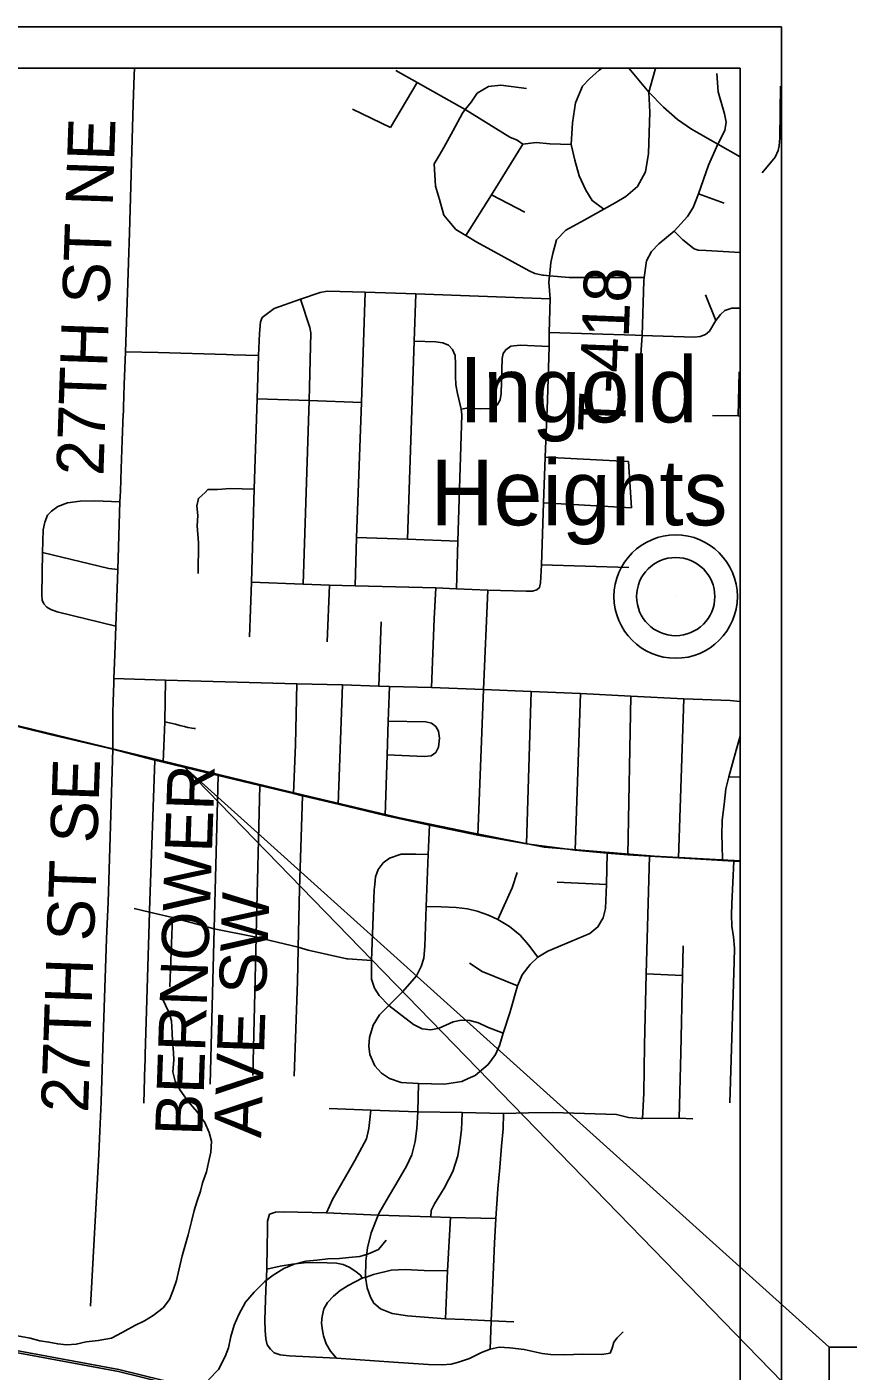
# Model space of a CAD drawing. Extents: x 25.6 to 80.6, y 0.2 to 24.5.
# Drawn here: x 46.093 to 48.073, y 14.588 to 17.83 of the extents above; entities that cross this region are included whole.
import ezdxf

# ---------------------------------------------------------------- set-up
doc = ezdxf.new("R2010")
doc.units = 0
for name, color, linetype in [('GM_X_Minor_Lake', 7, 'Continuous'), ('GM_X_Minor_River', 7, 'Continuous'), ('GM_X_Rail_Line', 7, 'Continuous'), ('GM_X_State_Route', 7, 'Continuous'), ('GM_X_Township_Road', 7, 'Continuous'), ('GM_X_Township_Road_Text', 7, 'Continuous'), ('GM_X_Unincorporated', 7, 'Continuous'), ('GM_X_Unincorporated_Location', 7, 'Continuous'), ('GM_X_Unincorporated_Text', 7, 'Continuous'), ('SH_Data', 7, 'Continuous'), ('SH_Text', 7, 'Continuous')]:
    doc.layers.add(name, color=color, linetype=linetype)

msp = doc.modelspace()

# ---------------------------------------------------------------- linework, layer by layer
at = {"layer": 'GM_X_Minor_Lake'}
msp.add_lwpolyline([(46.5313, 14.5669), (46.5552, 14.5923), (46.5715, 14.6237), (46.5795, 14.6443), (46.5852, 14.6718), (46.5925, 14.6992), (46.6043, 14.7245), (46.6205, 14.7543), (46.6407, 14.7789), (46.6669, 14.8044), (46.6872, 14.8198), (46.7128, 14.8354), (46.7376, 14.8464), (46.7656, 14.8529), (46.7921, 14.8555), (46.8187, 14.8589), (46.8467, 14.8601), (46.8694, 14.8619), (46.896, 14.8646), (46.9171, 14.8709), (46.9413, 14.8812), (46.9591, 14.9042)], dxfattribs=at)
at = {"layer": 'GM_X_Minor_River'}
msp.add_lwpolyline([(46.0701, 14.6736), (46.1013, 14.6672), (46.1241, 14.6615), (46.1462, 14.658), (46.1675, 14.6537), (46.1887, 14.6517), (46.2122, 14.6528), (46.2357, 14.6585), (46.2652, 14.6619), (46.297, 14.6677), (46.3226, 14.681), (46.3535, 14.6981), (46.3769, 14.7091), (46.3972, 14.7223), (46.4219, 14.7409), (46.4368, 14.7609), (46.4456, 14.783), (46.4537, 14.8067), (46.4594, 14.8318), (46.4673, 14.8661), (46.4752, 14.8944), (46.4818, 14.9165), (46.4897, 14.9493), (46.4961, 14.9752), (46.5034, 14.9989), (46.5114, 15.0225), (46.5165, 15.0424), (46.526, 15.0691), (46.531, 15.0912), (46.5367, 15.1163), (46.5379, 15.143), (46.5323, 15.1634), (46.5221, 15.1876), (46.5028, 15.2139), (46.4819, 15.2387), (46.4626, 15.2658), (46.4509, 15.2876), (46.4453, 15.3096), (46.4472, 15.3377), (46.4462, 15.3567), (46.4443, 15.384), (46.4433, 15.4038), (46.4414, 15.4326), (46.435, 15.4538), (46.4194, 15.4878)], dxfattribs=at)
at = {"layer": 'GM_X_Rail_Line'}
for points in [[(47.8128, 15.8191), (47.6057, 15.8302), (47.3402, 15.8521), (47.1631, 15.8871), (46.9912, 15.9223), (46.7273, 15.9853), (45.9383, 16.1769), (45.6136, 16.2567), (45.5036, 16.2842), (45.3992, 16.2924), (45.0499, 16.3176), (44.9789, 16.3252), (44.6728, 16.4383), (44.4128, 16.5397)], [(44.4128, 14.8771), (44.4231, 14.8756), (44.5249, 14.8648), (44.6048, 14.8557), (44.6465, 14.8507), (44.805, 14.8274), (45.0669, 14.7959), (45.2891, 14.7633), (46.0102, 14.6483), (46.3148, 14.5918), (46.4227, 14.5651), (46.528, 14.5372), (46.6857, 14.4857), (46.9234, 14.4078), (47.0403, 14.372), (47.1373, 14.3511), (47.2255, 14.3378), (47.2936, 14.3374), (47.3809, 14.3425), (47.4529, 14.3573), (47.553, 14.386), (47.7232, 14.4468), (47.8128, 14.4801)], [(44.4128, 14.8724), (44.4226, 14.871), (44.5243, 14.8601), (44.6043, 14.851), (44.6459, 14.846), (44.8044, 14.8227), (45.0663, 14.7912), (45.2884, 14.7586), (46.0094, 14.6437), (46.3138, 14.5872), (46.4216, 14.5606), (46.5266, 14.5327), (46.6843, 14.4812), (46.9219, 14.4033), (47.0391, 14.3674), (47.1365, 14.3464), (47.2252, 14.3331), (47.2937, 14.3327), (47.3816, 14.3378), (47.454, 14.3527), (47.5545, 14.3816), (47.7248, 14.4424), (47.8128, 14.4751)]]:
    msp.add_lwpolyline(points, dxfattribs=at)
at = {"layer": 'GM_X_State_Route'}
msp.add_line((47.5419, 15.8335), (47.5945, 15.8302), dxfattribs=at)
for points in [[(45.6971, 16.2334), (45.734, 16.2247), (45.9432, 16.1743), (46.1495, 16.1236), (46.3002, 16.0879), (46.4014, 16.0619)], [(46.4014, 16.0619), (46.4213, 16.0572), (46.5542, 16.025), (46.6549, 16.0006), (46.7363, 15.9813), (46.7578, 15.976), (46.8439, 15.9555), (46.9567, 15.9284), (47.0639, 15.9047), (47.1802, 15.8811), (47.2979, 15.86), (47.4151, 15.8444), (47.4923, 15.8373), (47.5419, 15.8335)], [(47.5945, 15.8302), (47.6644, 15.8261), (47.7707, 15.8197), (47.7979, 15.8181), (47.8128, 15.8173)]]:
    msp.add_lwpolyline(points, dxfattribs=at)
at = {"layer": 'GM_X_Township_Road'}
for p, q in [((46.3494, 17.6442), (46.3519, 17.714)), ((46.3519, 17.714), (46.3524, 17.7303)), ((46.9696, 17.5878), (47.0343, 17.696)), ((46.8782, 17.632), (46.9696, 17.5878)), ((47.2131, 17.4255), (47.2941, 17.3831)), ((47.7123, 17.4272), (47.7741, 17.4053)), ((47.7543, 17.1218), (47.7291, 17.1841)), ((47.3523, 17.0929), (47.5598, 17.0864)), ((46.5908, 17.0392), (46.6516, 17.0376)), ((47.8082, 16.8919), (47.8107, 16.9981)), ((47.3429, 16.7924), (47.5435, 16.7819)), ((47.5508, 16.6704), (47.5435, 16.7819)), ((47.3389, 16.682), (47.5508, 16.6704)), ((47.3339, 16.5329), (47.5444, 16.5263)), ((46.8174, 16.3474), (46.8231, 16.4837)), ((46.8231, 16.4837), (46.8848, 16.4823)), ((46.8848, 16.4823), (47.0792, 16.4772)), ((47.0792, 16.4772), (47.1291, 16.4751)), ((47.1291, 16.4751), (47.2045, 16.4718)), ((46.9415, 16.2402), (46.947, 16.3951)), ((46.8439, 15.9555), (46.854, 16.243)), ((46.9415, 16.2402), (46.9678, 16.2394)), ((47.1802, 15.8811), (47.1941, 16.2318)), ((47.3092, 16.2276), (47.2979, 15.86)), ((47.4278, 16.2221), (47.4151, 15.8444)), ((47.5492, 16.2159), (47.5419, 15.8335)), ((47.6644, 15.8261), (47.6771, 16.2098)), ((46.2897, 15.7447), (46.3002, 16.0879)), ((46.4014, 16.0619), (46.3885, 15.6991)), ((47.8128, 16.021), (47.7858, 16.0215)), ((46.6549, 16.0006), (46.6461, 15.6405)), ((47.5419, 15.8335), (47.5945, 15.8302)), ((47.4909, 15.7621), (47.3714, 15.7672)), ((46.4441, 15.6821), (46.4378, 15.5146)), ((47.5866, 15.5461), (47.6738, 15.5425)), ((46.2663, 15.1113), (46.2693, 15.1668)), ((46.2465, 14.7445), (46.2663, 15.1113))]:
    msp.add_line(p, q, dxfattribs=at)
for points in [[(46.9828, 17.725), (47.0343, 17.696), (47.1501, 17.6307), (47.2576, 17.5644), (47.2749, 17.5568), (47.2892, 17.5472), (47.321, 17.5514), (47.3543, 17.5483), (47.4051, 17.5469)], [(47.3548, 17.2444), (47.3565, 17.2623), (47.3611, 17.2836), (47.3703, 17.3169), (47.3923, 17.3396), (47.437, 17.3638), (47.4844, 17.391), (47.5117, 17.4056), (47.5376, 17.4213), (47.5658, 17.4456), (47.5847, 17.4803), (47.5917, 17.5251), (47.595, 17.6246), (47.593, 17.6725), (47.6081, 17.7276), (47.6093, 17.7303)], [(47.4844, 17.391), (47.456, 17.4115), (47.4409, 17.4366), (47.4244, 17.4707), (47.4146, 17.5087), (47.4051, 17.5469), (47.4088, 17.5989), (47.4158, 17.6467), (47.4325, 17.6876), (47.4499, 17.705), (47.4727, 17.7262), (47.4793, 17.7303)], [(47.8128, 17.5171), (47.7595, 17.5477), (47.6957, 17.5835), (47.6616, 17.6069), (47.6284, 17.6369), (47.593, 17.6725), (47.5442, 17.7303)], [(47.581, 17.2178), (47.5813, 17.2259), (47.587, 17.266), (47.5993, 17.2885), (47.6165, 17.3068), (47.6539, 17.3374), (47.6857, 17.3731), (47.6994, 17.3943), (47.7123, 17.4272), (47.737, 17.4971), (47.7595, 17.5477), (47.7761, 17.58), (47.7795, 17.6004), (47.7752, 17.6207), (47.7597, 17.6734), (47.7567, 17.7178)], [(47.0752, 17.4996), (47.0873, 17.52), (47.0987, 17.5397), (47.1208, 17.5806), (47.1435, 17.6223), (47.1501, 17.6307), (47.164, 17.6488), (47.1792, 17.67), (47.2065, 17.6866), (47.236, 17.6896), (47.2979, 17.6818)], [(47.8658, 17.478), (47.897, 17.516), (47.9045, 17.5321), (47.9069, 17.5434), (47.9089, 17.5623), (47.9101, 17.6874)], [(46.3379, 17.2609), (46.3379, 17.2629), (46.3407, 17.3339), (46.3494, 17.6442)], [(47.1517, 17.3273), (47.2131, 17.4255), (47.2892, 17.5472)], [(47.0752, 17.4996), (47.0781, 17.4457), (47.0878, 17.4138), (47.0983, 17.3759), (47.1104, 17.3615), (47.1277, 17.3417), (47.1517, 17.3273), (47.1783, 17.3113), (47.3043, 17.242), (47.3179, 17.2351), (47.3295, 17.233), (47.3367, 17.2317)], [(47.6539, 17.3374), (47.675, 17.3163), (47.7021, 17.295), (47.7119, 17.2919), (47.7308, 17.2911), (47.8128, 17.2857)], [(46.328, 16.9675), (46.3305, 17.0462), (46.3379, 17.2609)], [(47.1941, 16.2318), (47.2045, 16.4718), (47.297, 16.4693), (47.3126, 16.4696), (47.3225, 16.4723), (47.3289, 16.4778), (47.3319, 16.4892), (47.3339, 16.5329), (47.3389, 16.682), (47.3429, 16.7924), (47.3484, 16.9302), (47.3521, 17.0595), (47.3523, 17.0929), (47.3546, 17.174), (47.3519, 17.2146), (47.3534, 17.23), (47.354, 17.2365), (47.3548, 17.2444)], [(47.3367, 17.2317), (47.3391, 17.2313), (47.3534, 17.23), (47.401, 17.2258), (47.5813, 17.2259)], [(47.5722, 17.0166), (47.5764, 17.0859), (47.581, 17.2178)], [(46.6607, 17.1296), (46.6895, 17.1508), (46.7529, 17.1739), (46.8004, 17.1899), (46.8175, 17.1932), (46.9087, 17.1904), (47.0313, 17.1863), (47.3546, 17.174)], [(46.8848, 16.4823), (46.8877, 16.599), (46.8996, 16.9244), (46.9087, 17.1904)], [(47.0108, 16.5948), (47.0265, 17.0724), (47.0313, 17.1863)], [(46.7595, 16.4865), (46.7741, 16.9291), (46.7778, 17.0922), (46.7754, 17.1051), (46.7529, 17.1739)], [(47.5598, 17.0864), (47.5764, 17.0859), (47.7026, 17.0817), (47.7168, 17.0834), (47.7296, 17.0887), (47.739, 17.0962), (47.7543, 17.1218), (47.7652, 17.1362), (47.7763, 17.146), (47.7927, 17.1521), (47.8128, 17.1515)], [(46.6296, 16.3591), (46.6346, 16.4908), (46.6409, 16.7149), (46.6484, 16.9334), (46.6516, 17.0376), (46.6538, 17.0904), (46.6561, 17.119), (46.6607, 17.1296)], [(47.1291, 16.4751), (47.1322, 16.5899), (47.1419, 16.8947), (47.1406, 16.908), (47.1312, 16.9458), (47.1273, 16.9672), (47.1268, 16.9876), (47.1268, 17.0179), (47.1259, 17.0375), (47.1197, 17.0524), (47.1095, 17.0624), (47.096, 17.0685), (47.0789, 17.071), (47.0265, 17.0724)], [(47.1406, 16.908), (47.1538, 16.9109), (47.1863, 16.9093), (47.2136, 16.9098), (47.2272, 16.9181), (47.2343, 16.9307), (47.2363, 16.9457), (47.2388, 17.0302), (47.2414, 17.0423), (47.2477, 17.0516), (47.26, 17.0603), (47.2823, 17.0624), (47.3521, 17.0595)], [(46.3305, 17.0462), (46.4098, 17.0449), (46.5745, 17.0397), (46.5908, 17.0392)], [(46.3256, 16.8971), (46.3258, 16.9011), (46.3262, 16.913), (46.328, 16.9675)], [(46.6484, 16.9334), (46.7741, 16.9291), (46.8996, 16.9244)], [(46.3203, 16.7655), (46.3219, 16.81), (46.3229, 16.8323), (46.3256, 16.8971)], [(47.7462, 16.893), (47.8082, 16.8919), (47.8128, 16.8917)], [(46.3051, 16.3158), (46.3075, 16.385), (46.3122, 16.5213), (46.3174, 16.6845), (46.3184, 16.7108), (46.3203, 16.7655)], [(46.5064, 16.5119), (46.5066, 16.5862), (46.5036, 16.6272), (46.5049, 16.6514), (46.5032, 16.6747), (46.5066, 16.693), (46.5228, 16.7076), (46.5296, 16.7144), (46.553, 16.7143), (46.5833, 16.7165), (46.6409, 16.7149)], [(46.1308, 16.5627), (46.1326, 16.6169), (46.1363, 16.6354), (46.1427, 16.6522), (46.1525, 16.6622), (46.1674, 16.6731), (46.191, 16.6821), (46.2212, 16.6866), (46.2565, 16.6869), (46.3174, 16.6845)], [(46.8877, 16.599), (47.0108, 16.5948), (47.1322, 16.5899)], [(46.3075, 16.385), (46.166, 16.4192), (46.1509, 16.4248), (46.1408, 16.4306), (46.1339, 16.4386), (46.13, 16.4476), (46.1292, 16.4606), (46.1308, 16.5627)], [(46.1308, 16.5627), (46.2905, 16.524), (46.3122, 16.5213)], [(46.6346, 16.4908), (46.7595, 16.4865), (46.8231, 16.4837)], [(47.0686, 16.2366), (47.075, 16.4024), (47.0792, 16.4772)], [(46.3015, 16.2025), (46.3028, 16.2484), (46.3031, 16.2584), (46.3051, 16.3158)], [(46.3031, 16.2584), (46.4275, 16.2548), (46.744, 16.2454), (46.854, 16.243), (46.9415, 16.2402)], [(46.4275, 16.2548), (46.4254, 16.1541), (46.4213, 16.0572)], [(46.7363, 15.9813), (46.7405, 16.0997), (46.744, 16.2454)], [(46.9567, 15.9284), (46.9617, 16.0746), (46.9641, 16.1558), (46.9678, 16.2394)], [(46.9678, 16.2394), (47.0686, 16.2366), (47.1941, 16.2318), (47.3092, 16.2276), (47.4278, 16.2221), (47.5492, 16.2159), (47.6771, 16.2098), (47.7892, 16.2059), (47.8128, 16.2032)], [(46.3002, 16.0879), (46.3007, 16.1766), (46.3015, 16.2025)], [(46.4254, 16.1541), (46.4514, 16.1482), (46.462, 16.1456), (46.4732, 16.1426), (46.4809, 16.1404), (46.4915, 16.1386), (46.4962, 16.1382), (46.4993, 16.1381)], [(46.9617, 16.0746), (47.0512, 16.0705), (47.0682, 16.0722), (47.0789, 16.0802), (47.0856, 16.0929), (47.0876, 16.1147), (47.0853, 16.1315), (47.0794, 16.1428), (47.0689, 16.1508), (47.0549, 16.1543), (46.9641, 16.1558)], [(47.8128, 16.1194), (47.8035, 16.0861), (47.7858, 16.0215), (47.7788, 15.9929), (47.7742, 15.9546), (47.7699, 15.9171), (47.7691, 15.8799), (47.7699, 15.8583), (47.7707, 15.8197)], [(46.5542, 16.025), (46.5445, 15.6548), (46.5352, 15.2799)], [(46.7474, 15.6064), (46.7475, 15.6105), (46.7501, 15.7511), (46.7578, 15.976)], [(47.0639, 15.9047), (47.0606, 15.8342), (47.056, 15.7089), (47.0524, 15.6119), (47.0501, 15.5843), (47.044, 15.5638), (47.0329, 15.5414), (46.9995, 15.5034), (46.966, 15.4702), (46.9437, 15.4473), (46.9281, 15.4221), (46.919, 15.3929), (46.9176, 15.372), (46.9197, 15.3521)], [(47.0028, 15.8351), (46.9952, 15.8351), (46.9677, 15.8255), (46.9523, 15.8144), (46.9404, 15.7978), (46.9338, 15.7805), (46.932, 15.7621)], [(47.0606, 15.8342), (47.0311, 15.8349), (47.0028, 15.8351)], [(47.2333, 15.3755), (47.2414, 15.403), (47.2573, 15.452), (47.2759, 15.5172), (47.2876, 15.5438), (47.3064, 15.5687), (47.3248, 15.5866), (47.3495, 15.6013), (47.4047, 15.6242), (47.4501, 15.6434), (47.4699, 15.6594), (47.4829, 15.6811), (47.4886, 15.7038), (47.4909, 15.7621), (47.4923, 15.8373)], [(47.5945, 15.8302), (47.5866, 15.5461), (47.5826, 15.3741), (47.5806, 15.2585), (47.5773, 15.1971)], [(47.229, 15.6771), (47.263, 15.7537), (47.2749, 15.7907)], [(47.7881, 15.2353), (47.7989, 15.5755), (47.7996, 15.608), (47.7973, 15.6352), (47.793, 15.6611), (47.792, 15.6883), (47.7927, 15.7155), (47.7979, 15.8181)], [(46.932, 15.7621), (46.9307, 15.7492), (46.9237, 15.5783), (46.9242, 15.5333), (46.9311, 15.5119), (46.9423, 15.4939), (46.966, 15.4702), (47.025, 15.4242), (47.046, 15.4139), (47.0674, 15.4114), (47.0874, 15.4151), (47.1208, 15.4304), (47.1404, 15.4346), (47.161, 15.4341), (47.1822, 15.4284), (47.204, 15.4176), (47.2414, 15.403)], [(46.2693, 15.1668), (46.2721, 15.2372), (46.2773, 15.3934), (46.2847, 15.631), (46.2892, 15.7196), (46.2897, 15.7447)], [(46.8649, 15.5827), (46.7716, 15.6037), (46.7475, 15.6105), (46.6459, 15.6345), (46.5445, 15.6548), (46.4441, 15.6821), (46.3884, 15.6951), (46.3514, 15.7038)], [(46.3885, 15.6991), (46.3884, 15.6951), (46.3786, 15.352), (46.3781, 15.3356)], [(47.3248, 15.5866), (47.3024, 15.616), (47.2821, 15.6397), (47.2565, 15.6607), (47.229, 15.6771), (47.2058, 15.6878), (47.179, 15.6972), (47.1555, 15.703), (47.1282, 15.7062), (47.0921, 15.7078), (47.056, 15.7089)], [(46.6461, 15.6405), (46.6459, 15.6345), (46.6375, 15.3009)], [(46.7372, 15.2996), (46.7452, 15.5282), (46.7474, 15.6064)], [(47.6659, 15.1981), (47.6697, 15.3555), (47.6738, 15.5425), (47.6759, 15.6142)], [(46.9237, 15.5783), (46.8668, 15.5822), (46.8649, 15.5827)], [(47.2759, 15.5172), (47.1908, 15.5516), (47.1602, 15.5719)], [(47.157, 15.2936), (47.1741, 15.3011), (47.205, 15.3275), (47.2227, 15.3514), (47.2328, 15.3737), (47.2333, 15.3755)], [(46.3781, 15.3356), (46.3778, 15.3254), (46.3751, 15.2345)], [(46.9197, 15.3521), (46.9318, 15.3246), (46.9482, 15.307), (46.9672, 15.2941)], [(47.0373, 15.2815), (47.036, 15.2132), (47.0335, 15.1734), (47.0293, 15.1423), (47.0213, 15.1094), (47.0086, 15.0821), (46.9887, 15.0481), (46.9596, 14.9989), (46.9418, 14.9679)], [(46.9672, 15.2941), (46.9956, 15.2846), (47.0373, 15.2815), (47.1002, 15.2801), (47.1417, 15.2869), (47.157, 15.2936)], [(46.8159, 14.9699), (46.83, 15.0023), (46.8838, 15.0963), (46.9123, 15.1484), (46.9175, 15.1733), (46.9202, 15.1951), (46.9224, 15.2178)], [(46.8222, 15.2219), (46.9224, 15.2178), (47.036, 15.2132), (47.1426, 15.2116), (47.2424, 15.2093), (47.3028, 15.2114), (47.3604, 15.2116), (47.5145, 15.2072), (47.5437, 15.2002), (47.5731, 15.1975)], [(47.0669, 14.9601), (47.0681, 14.9756), (47.0763, 14.9916), (47.0994, 15.0292), (47.1202, 15.0698), (47.1323, 15.1076), (47.1372, 15.1383), (47.1411, 15.1703), (47.1421, 15.1895), (47.1426, 15.2116)], [(47.2424, 15.2093), (47.2412, 15.1726), (47.2374, 15.1304), (47.2332, 15.0791), (47.2286, 15.0276), (47.2237, 14.9559), (47.2207, 14.8965), (47.2163, 14.8008), (47.2128, 14.7095), (47.2103, 14.6408)], [(47.5731, 15.1975), (47.5773, 15.1971), (47.6659, 15.1981), (47.6989, 15.1965)], [(47.531, 14.6827), (47.5167, 14.6687), (47.5083, 14.6582), (47.5047, 14.6433), (47.4995, 14.6314), (47.4795, 14.6284), (47.4318, 14.6286), (47.3899, 14.6274), (47.356, 14.6281), (47.3356, 14.6307), (47.2922, 14.64), (47.2576, 14.6442), (47.2322, 14.6456), (47.2103, 14.6408), (47.189, 14.6328), (47.1606, 14.6188), (47.1342, 14.6095), (47.1165, 14.6046), (47.0946, 14.6036), (47.0613, 14.6041), (46.9769, 14.61), (46.8397, 14.6191), (46.7254, 14.6252), (46.7035, 14.6277), (46.6893, 14.6324), (46.6806, 14.6407), (46.6727, 14.6515), (46.6689, 14.666), (46.6676, 14.6858), (46.6671, 14.7107), (46.6694, 14.7842), (46.6718, 14.834), (46.6727, 14.8891), (46.6732, 14.9278), (46.6729, 14.9496), (46.6782, 14.9668)], [(47.2237, 14.9559), (47.1146, 14.9585), (47.0669, 14.9601), (46.9399, 14.9644), (46.8159, 14.9699), (46.7115, 14.9724), (46.6923, 14.9717), (46.6782, 14.9668)], [(46.9418, 14.9679), (46.9399, 14.9644), (46.9236, 14.9219), (46.9141, 14.8851), (46.9101, 14.8534), (46.9094, 14.8144), (46.9136, 14.7888), (46.9213, 14.7666), (46.9299, 14.7517), (46.9455, 14.7383), (46.9736, 14.7269), (47.0106, 14.7211), (47.1025, 14.7146), (47.1482, 14.7129), (47.2128, 14.7095), (47.2672, 14.7073)], [(47.1025, 14.7146), (47.1076, 14.8298), (47.1146, 14.9585)], [(46.6718, 14.834), (46.7039, 14.8414), (46.7333, 14.846), (46.7618, 14.8489), (46.7944, 14.8498), (46.8395, 14.8482), (46.8553, 14.8456), (46.8704, 14.8386), (46.8835, 14.83), (46.8971, 14.8197), (46.9013, 14.812)], [(47.1076, 14.8298), (47.0514, 14.8307), (47.005, 14.8335), (46.9715, 14.8314), (46.9285, 14.8208), (46.9113, 14.815)], [(46.9113, 14.815), (46.9094, 14.8144), (46.9013, 14.812), (46.8676, 14.7945), (46.8483, 14.7826), (46.8324, 14.7691), (46.818, 14.7539), (46.8089, 14.7383), (46.8051, 14.7196), (46.8038, 14.7042), (46.8049, 14.6907), (46.808, 14.6728), (46.8149, 14.6543), (46.8249, 14.6366), (46.8397, 14.6191)]]:
    msp.add_lwpolyline(points, dxfattribs=at)
at = {"layer": 'GM_X_Unincorporated'}
for radius in [0.1488, 0.0943]:
    msp.add_circle((47.6575, 16.4562), radius, dxfattribs=at)
at = {"layer": 'GM_X_Unincorporated_Location'}
msp.add_line((47.6575, 16.4562), (47.6575, 16.4562), dxfattribs=at)
at = {"layer": 'SH_Data'}
for p, q in [((44.5128, 17.8303), (47.9128, 17.8303)), ((47.9128, 17.8303), (47.9128, 14.2303))]:
    msp.add_line(p, q, dxfattribs=at)
at = {"layer": 'SH_Text'}
for points in [[(44.4128, 14.3303), (47.8128, 14.3303), (47.8128, 17.7303), (44.4128, 17.7303)], [(48.0273, 14.646), (48.0273, 14.446), (46.473, 16.0447)], [(50.7329, 14.646), (48.0273, 14.646), (48.0273, 13.9578), (50.7329, 13.9578)]]:
    msp.add_lwpolyline(points, close=True, dxfattribs=at)

# ---------------------------------------------------------------- texts
at = {"layer": 'GM_X_Township_Road_Text'}
for s, rotation, p in [('27TH ST NE', 88.0349, (46.2775, 16.7466)), ('T-418', 87.755, (47.5352, 16.8517)), ('27TH ST SE', 88.0349, (46.2405, 15.2104)), ('BERNOWER ', 88.0349, (46.5158, 15.1543)), ('AVE SW', 88.0349, (46.6578, 15.1494))]:
    msp.add_text(s, height=0.11364, rotation=rotation, dxfattribs=at).set_placement(p)
at = {"layer": 'GM_X_Unincorporated_Text'}
for s, p in [('Ingold', (47.1345, 16.8764)), ('Heights', (47.0662, 16.6281))]:
    msp.add_text(s, height=0.15795, rotation=0, dxfattribs=at).set_placement(p)

doc.saveas('drawing.dxf')
